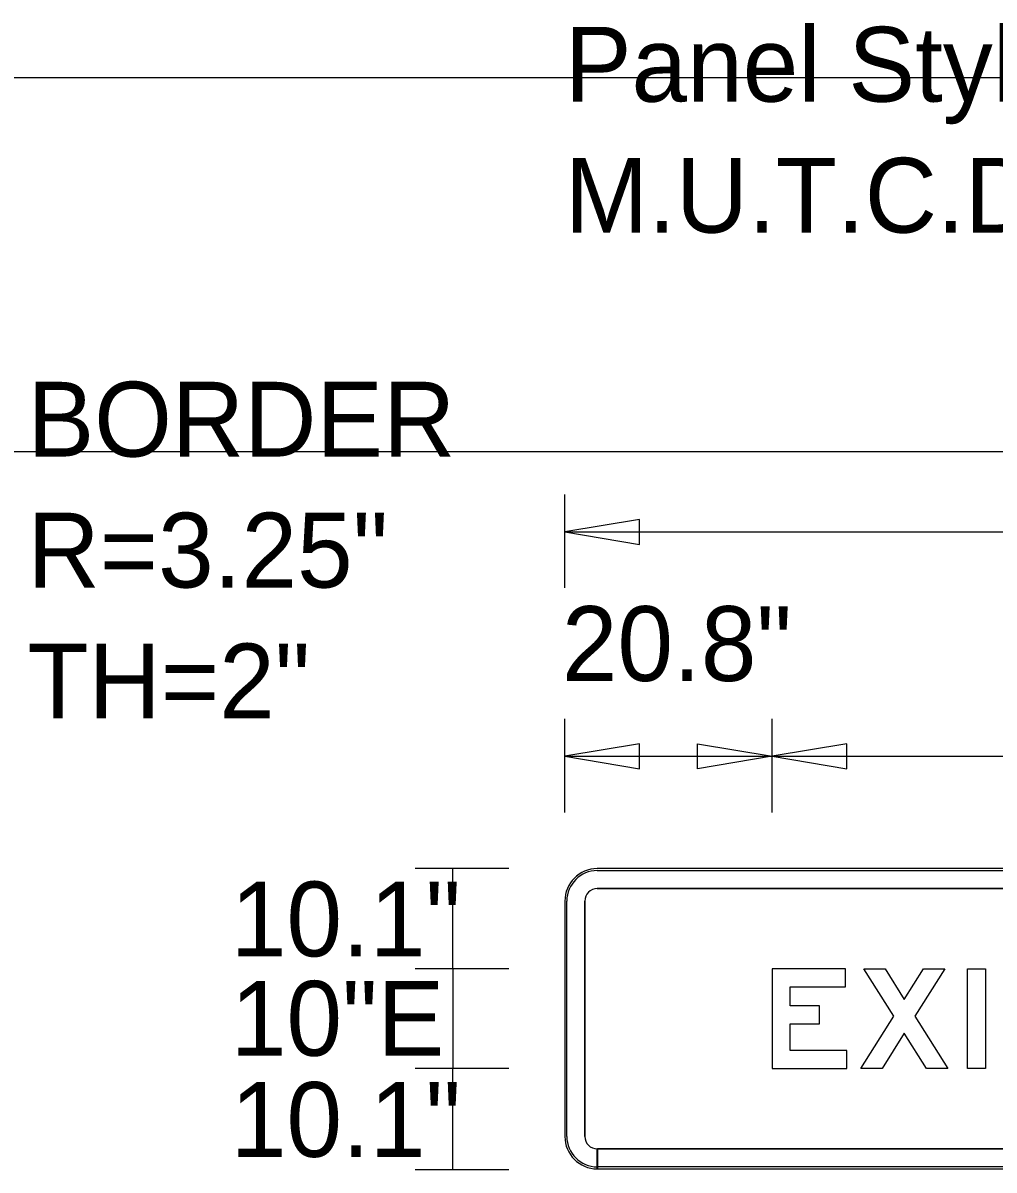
# Model space of a CAD drawing. Extents: x 1806251 to 1809821, y 414895 to 422886.
# Drawn here: x 1809677.229 to 1809678.204, y 414912.473 to 414913.623 of the extents above; entities that cross this region are included whole.
import ezdxf

# ---------------------------------------------------------------- set-up
doc = ezdxf.new("R2010")
doc.units = 0
for name, color, linetype in [('GSBWFILL', 7, 'Continuous'), ('GSCOLORFILL', 7, 'Continuous'), ('GSDIMS', 7, 'Continuous'), ('GSOUTLINE', 7, 'Continuous'), ('GSSHT', 7, 'Continuous')]:
    doc.layers.add(name, color=color, linetype=linetype)

msp = doc.modelspace()

# ---------------------------------------------------------------- linework, layer by layer
at = {"layer": 'GSBWFILL'}
for p, q in [((1809678.8815, 414912.7749), (1809677.8055, 414912.7749)), ((1809677.8055, 414912.7549), (1809678.8815, 414912.7549)), ((1809677.773, 414912.7424), (1809677.773, 414912.5064)), ((1809677.793, 414912.5064), (1809677.793, 414912.7424)), ((1809677.8055, 414912.4739), (1809677.8055, 414912.4939)), ((1809678.8815, 414912.4939), (1809677.8057, 414912.4939)), ((1809677.8057, 414912.4939), (1809677.8057, 414912.4739)), ((1809677.8057, 414912.4739), (1809678.8815, 414912.4739))]:
    msp.add_line(p, q, dxfattribs=at)
for points in [[(1809678.056, 414912.5924), (1809677.999, 414912.5924), (1809677.999, 414912.6193), (1809678.0285, 414912.6193), (1809678.0285, 414912.6373), (1809677.999, 414912.6373), (1809677.999, 414912.6564), (1809678.0545, 414912.6564), (1809678.0545, 414912.6744), (1809677.981, 414912.6744), (1809677.981, 414912.5744), (1809678.056, 414912.5744)], [(1809678.1358, 414912.5744), (1809678.1135, 414912.6099), (1809678.0913, 414912.5744), (1809678.07, 414912.5744), (1809678.1029, 414912.6268), (1809678.073, 414912.6744), (1809678.0943, 414912.6744), (1809678.1135, 414912.6437), (1809678.1328, 414912.6744), (1809678.154, 414912.6744), (1809678.1242, 414912.6268), (1809678.157, 414912.5744)], [(1809678.177, 414912.5744), (1809678.177, 414912.6744), (1809678.195, 414912.6744), (1809678.195, 414912.5744)]]:
    msp.add_lwpolyline(points, close=True, dxfattribs=at)
for centre, radius, start, end in [((1809677.8055, 414912.7424), 0.0325, 90, 180), ((1809677.8055, 414912.7424), 0.0125, 90, 180), ((1809677.8055, 414912.5064), 0.0325, 180, 270), ((1809677.8055, 414912.5064), 0.0125, 180, 270)]:
    msp.add_arc(centre, radius, start, end, dxfattribs=at)
at = {"layer": 'GSCOLORFILL'}
for p, q in [((1809678.8815, 414912.7749), (1809677.8055, 414912.7749)), ((1809678.8815, 414912.7749), (1809677.8055, 414912.7749)), ((1809678.8815, 414912.7749), (1809677.8055, 414912.7749)), ((1809677.8055, 414912.7729), (1809678.8815, 414912.7729)), ((1809677.8055, 414912.7549), (1809678.8815, 414912.7549)), ((1809677.773, 414912.7424), (1809677.773, 414912.5064)), ((1809677.773, 414912.7424), (1809677.773, 414912.5064)), ((1809677.773, 414912.7424), (1809677.773, 414912.5064)), ((1809677.775, 414912.5064), (1809677.775, 414912.7424)), ((1809677.793, 414912.5064), (1809677.793, 414912.7424)), ((1809677.8055, 414912.4739), (1809677.8055, 414912.4939)), ((1809678.8815, 414912.4939), (1809677.8057, 414912.4939)), ((1809677.8057, 414912.4939), (1809677.8057, 414912.4739)), ((1809677.8055, 414912.4739), (1809677.8055, 414912.4759)), ((1809678.8815, 414912.4759), (1809677.8056, 414912.4759)), ((1809677.8056, 414912.4759), (1809677.8056, 414912.4739)), ((1809677.8055, 414912.4739), (1809678.8815, 414912.4739)), ((1809677.8056, 414912.4739), (1809678.8815, 414912.4739)), ((1809677.8057, 414912.4739), (1809678.8815, 414912.4739))]:
    msp.add_line(p, q, dxfattribs=at)
for points in [[(1809678.056, 414912.5924), (1809677.999, 414912.5924), (1809677.999, 414912.6193), (1809678.0285, 414912.6193), (1809678.0285, 414912.6373), (1809677.999, 414912.6373), (1809677.999, 414912.6564), (1809678.0545, 414912.6564), (1809678.0545, 414912.6744), (1809677.981, 414912.6744), (1809677.981, 414912.5744), (1809678.056, 414912.5744)], [(1809678.1358, 414912.5744), (1809678.1135, 414912.6099), (1809678.0913, 414912.5744), (1809678.07, 414912.5744), (1809678.1029, 414912.6268), (1809678.073, 414912.6744), (1809678.0943, 414912.6744), (1809678.1135, 414912.6437), (1809678.1328, 414912.6744), (1809678.154, 414912.6744), (1809678.1242, 414912.6268), (1809678.157, 414912.5744)], [(1809678.177, 414912.5744), (1809678.177, 414912.6744), (1809678.195, 414912.6744), (1809678.195, 414912.5744)]]:
    msp.add_lwpolyline(points, close=True, dxfattribs=at)
for centre, radius, start, end in [((1809677.8055, 414912.7424), 0.0325, 90, 180), ((1809677.8055, 414912.7424), 0.0325, 90, 180), ((1809677.8055, 414912.7424), 0.0325, 90, 180), ((1809677.8055, 414912.7424), 0.0305, 90, 180), ((1809677.8055, 414912.7424), 0.0125, 90, 180), ((1809677.8055, 414912.5064), 0.0325, 180, 270), ((1809677.8055, 414912.5064), 0.0325, 180, 270), ((1809677.8055, 414912.5064), 0.0325, 180, 270), ((1809677.8055, 414912.5064), 0.0305, 180, 270), ((1809677.8055, 414912.5064), 0.0125, 180, 270)]:
    msp.add_arc(centre, radius, start, end, dxfattribs=at)
at = {"layer": 'GSDIMS'}
for p, q in [((1809677.773, 414913.0563), (1809677.773, 414913.15)), ((1809677.773, 414913.1125), (1809678.915, 414913.1125)), ((1809677.773, 414912.8312), (1809677.773, 414912.925)), ((1809677.981, 414912.8312), (1809677.981, 414912.925)), ((1809677.981, 414912.8312), (1809677.981, 414912.925)), ((1809677.773, 414912.8875), (1809677.981, 414912.8875)), ((1809677.981, 414912.8875), (1809678.706, 414912.8875)), ((1809677.7168, 414912.775), (1809677.623, 414912.775)), ((1809677.6605, 414912.6744), (1809677.6605, 414912.775)), ((1809677.7168, 414912.6744), (1809677.623, 414912.6744)), ((1809677.7168, 414912.6744), (1809677.623, 414912.6744)), ((1809677.6605, 414912.6744), (1809677.6605, 414912.5744)), ((1809677.7168, 414912.5744), (1809677.623, 414912.5744)), ((1809677.7168, 414912.5744), (1809677.623, 414912.5744)), ((1809677.6605, 414912.473), (1809677.6605, 414912.5744)), ((1809677.7168, 414912.473), (1809677.623, 414912.473))]:
    msp.add_line(p, q, dxfattribs=at)
for points in [[(1809677.773, 414913.1125), (1809677.848, 414913.1), (1809677.848, 414913.125)], [(1809677.773, 414912.8875), (1809677.848, 414912.875), (1809677.848, 414912.9)], [(1809677.981, 414912.8875), (1809677.906, 414912.875), (1809677.906, 414912.9)], [(1809677.981, 414912.8875), (1809678.056, 414912.875), (1809678.056, 414912.9)]]:
    msp.add_lwpolyline(points, close=True, dxfattribs=at)
at = {"layer": 'GSOUTLINE'}
for p, q in [((1809678.8815, 414912.7749), (1809677.8055, 414912.7749)), ((1809678.8815, 414912.7549), (1809677.8055, 414912.7549)), ((1809677.773, 414912.7424), (1809677.773, 414912.5064)), ((1809677.793, 414912.7424), (1809677.793, 414912.5064)), ((1809677.8055, 414912.4939), (1809678.8815, 414912.4939)), ((1809677.8055, 414912.4739), (1809678.8815, 414912.4739))]:
    msp.add_line(p, q, dxfattribs=at)
for points in [[(1809678.056, 414912.5924), (1809677.999, 414912.5924), (1809677.999, 414912.6193), (1809678.0285, 414912.6193), (1809678.0285, 414912.6373), (1809677.999, 414912.6373), (1809677.999, 414912.6564), (1809678.0545, 414912.6564), (1809678.0545, 414912.6744), (1809677.981, 414912.6744), (1809677.981, 414912.5744), (1809678.056, 414912.5744)], [(1809678.1358, 414912.5744), (1809678.1135, 414912.6099), (1809678.0913, 414912.5744), (1809678.07, 414912.5744), (1809678.1029, 414912.6268), (1809678.073, 414912.6744), (1809678.0943, 414912.6744), (1809678.1135, 414912.6437), (1809678.1328, 414912.6744), (1809678.154, 414912.6744), (1809678.1242, 414912.6268), (1809678.157, 414912.5744)], [(1809678.177, 414912.5744), (1809678.177, 414912.6744), (1809678.195, 414912.6744), (1809678.195, 414912.5744)]]:
    msp.add_lwpolyline(points, close=True, dxfattribs=at)
for centre, radius, start, end in [((1809677.8055, 414912.7424), 0.0325, 90, 180), ((1809677.8055, 414912.7424), 0.0125, 90, 180), ((1809677.8055, 414912.5064), 0.0325, 180, 270), ((1809677.8055, 414912.5064), 0.0125, 180, 270)]:
    msp.add_arc(centre, radius, start, end, dxfattribs=at)
at = {"layer": 'GSSHT'}
msp.add_line((1809672.1348, 414913.5682), (1809684.889, 414913.5682), dxfattribs=at)
msp.add_lwpolyline([(1809672.6339, 414913.1931), (1809684.638, 414913.1931), (1809684.638, 414905.6894), (1809672.6339, 414905.6894)], close=True, dxfattribs=at)

# ---------------------------------------------------------------- texts
at = {"layer": 'GSDIMS'}
for s, p in [('Panel Style: tab1.bsi', (1809677.773, 414913.5438)), ('M.U.T.C.D.: 2009 Edition', (1809677.773, 414913.4125)), ('BORDER', (1809677.234, 414913.188)), ('R=3.25"', (1809677.234, 414913.0567)), ('20.8"', (1809677.77, 414912.963)), ('TH=2"', (1809677.234, 414912.9255)), ('10.1"', (1809677.438, 414912.6869)), ('10"E', (1809677.438, 414912.5873)), ('10.1"', (1809677.438, 414912.4859))]:
    msp.add_text(s, height=0.075, dxfattribs=at).set_placement(p)

doc.saveas('drawing.dxf')
